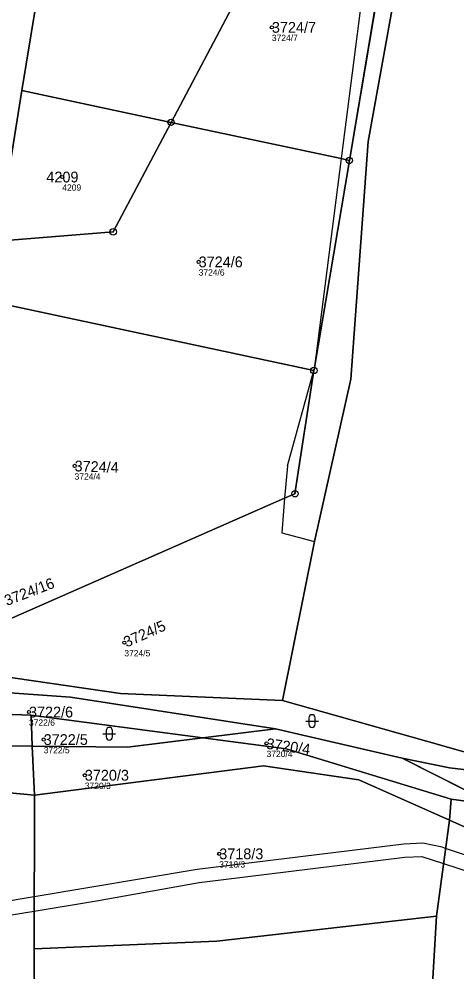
# Model space of a CAD drawing. Extents: x -761174 to -757114, y -1063806 to -1059397.
# Drawn here: x -759859.8 to -759790.8, y -1060240.2 to -1060089.9 of the extents above; entities that cross this region are included whole.
import ezdxf

# ---------------------------------------------------------------- set-up
doc = ezdxf.new("R2010")
doc.units = 0
for name, color, linetype in [('Definiční body', 7, 'Continuous'), ('Hranice parcel', 7, 'Continuous'), ('Parcelní čísla', 7, 'Continuous'), ('Polygon ku', 7, 'Continuous'), ('Polygon parcely', 7, 'Continuous'), ('Vnitřní kresba', 7, 'Continuous'), ('Věcná břemena k části', 7, 'Continuous'), ('Značky bodu BP', 7, 'Continuous'), ('Značky kultur', 7, 'Continuous')]:
    doc.layers.add(name, color=color, linetype=linetype)

msp = doc.modelspace()

# ---------------------------------------------------------------- linework, layer by layer
at = {"layer": 'Definiční body'}
for centre in [(-759819.97, -1060091.23), (-759853, -1060114.83), (-759831.51, -1060128.21), (-759851.06, -1060160.38), (-759843.22, -1060188.25), (-759858.25, -1060199.19), (-759855.93, -1060203.53), (-759820.81, -1060204.13), (-759849.45, -1060209.15), (-759828.27, -1060221.55)]:
    msp.add_circle(centre, 0.25, dxfattribs=at)
at = {"layer": 'Hranice parcel'}
for p, q in [((-759819.63, -1060075.47), (-759835.86, -1060106.21)), ((-759807.76, -1060112.21), (-759802.18, -1060079.2)), ((-759863.21, -1060124.94), (-759859.35, -1060101.19)), ((-759859.35, -1060101.19), (-759835.86, -1060106.21)), ((-759813.32, -1060145.16), (-759807.76, -1060112.21)), ((-759813.35, -1060145.33), (-759864.74, -1060134.35)), ((-759813.35, -1060145.33), (-759816.33, -1060164.77)), ((-759813.35, -1060145.33), (-759813.32, -1060145.16)), ((-759857.89, -1060199.7), (-759886.32, -1060198.67)), ((-759857.73, -1060204.58), (-759857.89, -1060199.7)), ((-759830.86, -1060203.26), (-759857.89, -1060199.7)), ((-759819.39, -1060201.86), (-759830.86, -1060203.26)), ((-759799.43, -1060206.47), (-759819.39, -1060201.86)), ((-759857.73, -1060204.58), (-759862.33, -1060204.54)), ((-759857.38, -1060212.31), (-759857.73, -1060204.58)), ((-759784.79, -1060213.87), (-759799.43, -1060206.47)), ((-759857.44, -1060236.53), (-759857.38, -1060212.31)), ((-759791.99, -1060216.26), (-759791.74, -1060212.92)), ((-759791.74, -1060212.92), (-759784.79, -1060213.87)), ((-759791.99, -1060216.26), (-759794.05, -1060231.35))]:
    msp.add_line(p, q, dxfattribs=at)
for points in [[(-759787.12, -1060014.11), (-759789.61, -1060029.28), (-759798.55, -1060074.57), (-759804.77, -1060109.23), (-759807.53, -1060146.72), (-759813.24, -1060172.29), (-759818.32, -1060197.38)], [(-759859.35, -1060101.19), (-759855.19, -1060075.6), (-759853.79, -1060068.18)], [(-759835.86, -1060106.21), (-759844.98, -1060123.47), (-759863.21, -1060124.94)], [(-759807.76, -1060112.21), (-759809.05, -1060111.93), (-759835.86, -1060106.21)], [(-759816.33, -1060164.77), (-759817.96, -1060165.49), (-759863.5, -1060185.49)], [(-759818.32, -1060197.38), (-759843.85, -1060196.29), (-759877.06, -1060191.44)], [(-759819.39, -1060201.86), (-759851.72, -1060196.83), (-759884.11, -1060194.53)], [(-759818.32, -1060197.38), (-759795.6, -1060203.76), (-759779.51, -1060208.37), (-759771.21, -1060210.43)], [(-759830.86, -1060203.26), (-759842.72, -1060204.71), (-759857.73, -1060204.58)], [(-759791.74, -1060212.92), (-759817.73, -1060204.99), (-759830.86, -1060203.26)], [(-759857.38, -1060212.31), (-759821.3, -1060207.67), (-759806.26, -1060209.9), (-759791.99, -1060216.26)], [(-759799.43, -1060206.47), (-759791.96, -1060207.99), (-759771.21, -1060210.43)], [(-760047.48, -1060214.16), (-760031.29, -1060211.63), (-759995.18, -1060211.78), (-759956.52, -1060213.25), (-759935.07, -1060212.99), (-759900.15, -1060209.94), (-759886.18, -1060209.63), (-759857.38, -1060212.31)], [(-759791.99, -1060216.26), (-759781.01, -1060221.15), (-759774.8, -1060223.92)], [(-759794.05, -1060231.35), (-759796.23, -1060268.9), (-759797.73, -1060310.53), (-759797.5, -1060364.55), (-759851.13, -1060368.72), (-759856.97, -1060321.59), (-759857.44, -1060236.53)], [(-759794.05, -1060231.35), (-759828.64, -1060235.33), (-759857.44, -1060236.53)]]:
    msp.add_lwpolyline(points, dxfattribs=at)
at = {"layer": 'Polygon ku'}
msp.add_lwpolyline([(-759787.12, -1060014.11), (-759793.09, -1060025.34), (-759796.57, -1060045.95), (-759802.18, -1060079.2), (-759804.77, -1060078.65), (-759819.63, -1060075.47), (-759853.79, -1060068.18), (-759855.19, -1060075.6), (-759859.35, -1060101.19), (-759863.21, -1060124.94), (-759867.32, -1060125.27), (-759865.97, -1060116.94), (-759901.28, -1060113.86), (-759917.62, -1060111.15), (-759945.84, -1060106.46), (-759966.43, -1060102.05), (-759983.22, -1060098.46)], dxfattribs=at)
at = {"layer": 'Polygon parcely'}
for points in [[(-759817.96, -1060165.49), (-759863.5, -1060185.49), (-759872.18, -1060189.3), (-759877.06, -1060191.44), (-759843.85, -1060196.29), (-759818.32, -1060197.38), (-759813.24, -1060172.29), (-759807.53, -1060146.72), (-759804.77, -1060109.23), (-759798.55, -1060074.57), (-759789.61, -1060029.28), (-759787.12, -1060014.11), (-759793.09, -1060025.34), (-759796.57, -1060045.95), (-759802.18, -1060079.2), (-759807.76, -1060112.21), (-759813.32, -1060145.16), (-759813.35, -1060145.33), (-759816.33, -1060164.77)], [(-759835.86, -1060106.21), (-759819.63, -1060075.47), (-759853.79, -1060068.18), (-759855.19, -1060075.6), (-759859.35, -1060101.19)], [(-759819.63, -1060075.47), (-759835.86, -1060106.21), (-759809.05, -1060111.93), (-759807.76, -1060112.21), (-759802.18, -1060079.2), (-759804.77, -1060078.65)], [(-759859.35, -1060101.19), (-759863.21, -1060124.94), (-759844.98, -1060123.47), (-759835.86, -1060106.21)], [(-759844.98, -1060123.47), (-759863.21, -1060124.94), (-759864.74, -1060134.35), (-759813.35, -1060145.33), (-759813.32, -1060145.16), (-759807.76, -1060112.21), (-759809.05, -1060111.93), (-759835.86, -1060106.21)], [(-759872.96, -1060187.15), (-759872.18, -1060189.3), (-759863.5, -1060185.49), (-759817.96, -1060165.49), (-759816.33, -1060164.77), (-759813.35, -1060145.33), (-759864.74, -1060134.35), (-759872.58, -1060182.67), (-759872.93, -1060184.86)], [(-759799.43, -1060206.47), (-759791.96, -1060207.99), (-759771.21, -1060210.43), (-759779.51, -1060208.37), (-759795.6, -1060203.76), (-759818.32, -1060197.38), (-759843.85, -1060196.29), (-759877.06, -1060191.44), (-759882.48, -1060193.82), (-759884.11, -1060194.53), (-759851.72, -1060196.83), (-759819.39, -1060201.86)], [(-759953.35, -1060203.05), (-759956.88, -1060203.98), (-759993.86, -1060203.35), (-760006.62, -1060201.71), (-760077.92, -1060197.29), (-760078.34, -1060204.05), (-760040.37, -1060204.16), (-760031.9, -1060202.05), (-759982.23, -1060206.08), (-759948.34, -1060204.15), (-759912.45, -1060201.46), (-759890.79, -1060197.58), (-759886.32, -1060198.67), (-759857.89, -1060199.7), (-759830.86, -1060203.26), (-759819.39, -1060201.86), (-759851.72, -1060196.83), (-759884.11, -1060194.53), (-759890.19, -1060194.63), (-759913.71, -1060199.32), (-759922.08, -1060200.11)], [(-759857.73, -1060204.58), (-759857.89, -1060199.7), (-759886.32, -1060198.67), (-759862.33, -1060204.54)], [(-759830.86, -1060203.26), (-759857.89, -1060199.7), (-759857.73, -1060204.58), (-759842.72, -1060204.71)], [(-759784.79, -1060213.87), (-759799.43, -1060206.47), (-759819.39, -1060201.86), (-759830.86, -1060203.26), (-759817.73, -1060204.99), (-759791.74, -1060212.92)], [(-759857.73, -1060204.58), (-759862.33, -1060204.54), (-759886.85, -1060205.03), (-759910.29, -1060206.52), (-759952.81, -1060209.14), (-759955.12, -1060209.28), (-759984.17, -1060210.15), (-760003.82, -1060209.81), (-760033.18, -1060209.12), (-760047.73, -1060207.44), (-760047.48, -1060214.16), (-760031.29, -1060211.63), (-759995.18, -1060211.78), (-759956.52, -1060213.25), (-759935.07, -1060212.99), (-759900.15, -1060209.94), (-759886.18, -1060209.63), (-759857.38, -1060212.31)], [(-759830.86, -1060203.26), (-759842.72, -1060204.71), (-759857.73, -1060204.58), (-759857.38, -1060212.31), (-759821.3, -1060207.67), (-759806.26, -1060209.9), (-759791.99, -1060216.26), (-759791.74, -1060212.92), (-759817.73, -1060204.99)], [(-759791.99, -1060216.26), (-759806.26, -1060209.9), (-759821.3, -1060207.67), (-759857.38, -1060212.31), (-759857.44, -1060236.53), (-759828.64, -1060235.33), (-759794.05, -1060231.35)], [(-759771.25, -1060215.73), (-759771.21, -1060210.43), (-759791.96, -1060207.99), (-759799.43, -1060206.47), (-759784.79, -1060213.87)], [(-759781.01, -1060221.15), (-759774.8, -1060223.92), (-759774.77, -1060218.94), (-759784.79, -1060213.87), (-759791.74, -1060212.92), (-759791.99, -1060216.26)], [(-759828.64, -1060235.33), (-759857.44, -1060236.53), (-759856.97, -1060321.59), (-759851.13, -1060368.72), (-759797.5, -1060364.55), (-759797.73, -1060310.53), (-759796.23, -1060268.9), (-759794.05, -1060231.35)]]:
    msp.add_lwpolyline(points, close=True, dxfattribs=at)
for points in [[(-759789.61, -1060029.28), (-759798.55, -1060074.57), (-759804.77, -1060109.23), (-759807.53, -1060146.72), (-759813.24, -1060172.29), (-759818.32, -1060197.38), (-759795.6, -1060203.76), (-759779.51, -1060208.37)], [(-759781.01, -1060221.15), (-759791.99, -1060216.26), (-759794.05, -1060231.35), (-759796.23, -1060268.9), (-759797.73, -1060310.53), (-759797.5, -1060364.55), (-759851.13, -1060368.72), (-759856.97, -1060321.59), (-759857.44, -1060236.53), (-759857.38, -1060212.31), (-759886.18, -1060209.63), (-759900.15, -1060209.94), (-759935.07, -1060212.99), (-759956.52, -1060213.25), (-759995.18, -1060211.78), (-760031.29, -1060211.63), (-760047.48, -1060214.16), (-760047.35, -1060219.62), (-760043.23, -1060220.31), (-760044.54, -1060229.26), (-760048.73, -1060229.18), (-760022.24, -1060392.99)]]:
    msp.add_lwpolyline(points, dxfattribs=at)
at = {"layer": 'Vnitřní kresba'}
for p, q in [((-759804.77, -1060078.65), (-759809.05, -1060111.93)), ((-759809.05, -1060111.93), (-759813.32, -1060145.16)), ((-759817.53, -1060160.35), (-759813.35, -1060145.33)), ((-759817.53, -1060160.35), (-759817.96, -1060165.49)), ((-759817.96, -1060165.49), (-759818.41, -1060170.91)), ((-759818.41, -1060170.91), (-759813.24, -1060172.29))]:
    msp.add_line(p, q, dxfattribs=at)
at = {"layer": 'Věcná břemena k části'}
for points in [[(-759774.82, -1060226.57), (-759792.6, -1060220.69), (-759793.13, -1060220.51), (-759796.2, -1060219.87), (-759799.19, -1060220.01), (-759831.74, -1060224.04), (-759857.42, -1060228.33), (-759875.9, -1060231.42)], [(-759879.22, -1060234.1), (-759857.43, -1060230.56), (-759847.61, -1060228.96), (-759831.43, -1060226.08), (-759799.01, -1060222.07), (-759796.36, -1060221.95), (-759792.92, -1060223.07), (-759777.26, -1060228.16)]]:
    msp.add_lwpolyline(points, dxfattribs=at)
at = {"layer": 'Značky bodu BP'}
for centre, radius in [((-759835.86, -1060106.21), 0.5), ((-759835.86, -1060106.21), 0.0303), ((-759807.76, -1060112.21), 0.5), ((-759807.76, -1060112.21), 0.0303), ((-759844.98, -1060123.47), 0.5), ((-759844.98, -1060123.47), 0.0303), ((-759813.35, -1060145.33), 0.5), ((-759813.35, -1060145.33), 0.0303), ((-759816.33, -1060164.77), 0.5), ((-759816.33, -1060164.77), 0.0303)]:
    msp.add_circle(centre, radius, dxfattribs=at)
at = {"layer": 'Značky kultur'}
for p, q in [((-759814.14, -1060200.11), (-759814.14, -1060201.11)), ((-759813.14, -1060201.11), (-759813.14, -1060200.11)), ((-759814.64, -1060200.61), (-759812.64, -1060200.61)), ((-759846.59, -1060202.61), (-759844.59, -1060202.61)), ((-759846.09, -1060202.11), (-759846.09, -1060203.11)), ((-759845.09, -1060203.11), (-759845.09, -1060202.11))]:
    msp.add_line(p, q, dxfattribs=at)
for centre, start, end in [((-759813.64, -1060200.11), 0, 180), ((-759845.59, -1060202.11), 0, 180), ((-759813.64, -1060201.11), 180, 359.9879), ((-759845.59, -1060203.11), 180, 359.9879)]:
    msp.add_arc(centre, 0.5, start, end, dxfattribs=at)

# ---------------------------------------------------------------- texts
at = {"layer": 'Definiční body'}
for s, p in [('3724/7', (-759819.97, -1060093.39)), ('4209', (-759853, -1060116.99)), ('3724/6', (-759831.51, -1060130.37)), ('3724/4', (-759851.06, -1060162.54)), ('3724/5', (-759843.22, -1060190.41)), ('3722/6', (-759858.25, -1060201.35)), ('3722/5', (-759855.93, -1060205.69)), ('3720/4', (-759820.81, -1060206.29)), ('3720/3', (-759849.45, -1060211.31)), ('3718/3', (-759828.27, -1060223.71))]:
    msp.add_text(s, height=1, dxfattribs=at).set_placement(p)
at = {"layer": 'Parcelní čísla'}
for s, p in [('3724/7', (-759819.97, -1060092.08)), ('4209', (-759855.51, -1060115.68)), ('3724/6', (-759831.51, -1060129.06)), ('3722/6', (-759858.25, -1060200.04)), ('3722/5', (-759855.93, -1060204.38)), ('3720/3', (-759849.45, -1060210)), ('3718/3', (-759828.27, -1060222.4))]:
    msp.add_text(s, height=1.7, dxfattribs=at).set_placement(p)
for s, rotation, p in [('3724/4', 358, (-759851.09, -1060161.23)), ('3724/16', 21, (-759861.74, -1060182.48)), ('3724/5', 24, (-759842.87, -1060189.03)), ('3720/4', 352, (-759820.93, -1060204.97))]:
    msp.add_text(s, height=1.7, rotation=rotation, dxfattribs=at).set_placement(p)

doc.saveas('drawing.dxf')
